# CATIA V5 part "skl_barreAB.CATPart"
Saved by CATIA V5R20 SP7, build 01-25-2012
Part number: skl_barreAB
Publications: "Axe pivot AB/Bati", "Axe pivot AB/BC", "Plan AB"
Bounding box of the stored display mesh (mm): x 0 to 0, y 0 to 12.665, z 0 to 18.428
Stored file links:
  U:\IAO_bon\skl_barreAB.CATPart
  U:\IAO_bon\skl_IAO.CATProduct
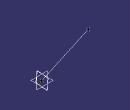
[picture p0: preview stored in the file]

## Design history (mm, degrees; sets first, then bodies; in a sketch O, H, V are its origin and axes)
Set1
  Point1 "Point A": linked copy from another document
  Point2 "Point B/G": linked copy from another document
  Plane1 "Plan Ref": linked copy from another document
Set2
  Line1: type PtPt, FirstPoint Point1, SecondPoint Point2
  Line2 "Axe pivot AB/Bati": type Normal, RefPoint Point1, RefSkin Plane1, Start 0, End 20
  Line3 "Axe pivot AB/BC": type Normal, RefPoint Point2, RefSkin Plane1, Start 0, End 20
  Plane2 "Plan AB": type Offset, RefPlane yz-plane, Offset 0
Body1 (main body)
